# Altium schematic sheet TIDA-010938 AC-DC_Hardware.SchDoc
size 431 x 279 mm; Date: Not shown in title block; ApprovedBy: Not shown in title block; CheckedBy: Not shown in title block; Author: Not shown in title block; CompanyName: Not shown in title block; Engineer: Not shown in title block; Organization: Not shown in title block; Address1: Not shown in title block; Address2: Not shown in title block; Address3: Not shown in title block; Address4: Not shown in title block; DocumentNumber: 11; Revision: Use project parameter SCH_Rev; SheetNumber: 11; SheetTotal: 11; PageSetup: Record=PageOptions¦CenterHorizontal=True¦CenterVertical=True¦PrintScale=1.00¦XCorrection=1.00¦YCorrection=1.00¦PrintKind=0¦BorderSize=5000000¦LeftOffset=0¦BottomOffset=0¦Orientation=2¦PaperLength=1000¦PaperWidth=1000¦Scale=100¦PaperSource=15¦PrintQuality=600¦MediaType=1¦DitherType=10¦PaperKind=Letter¦PrintScaleMode=1
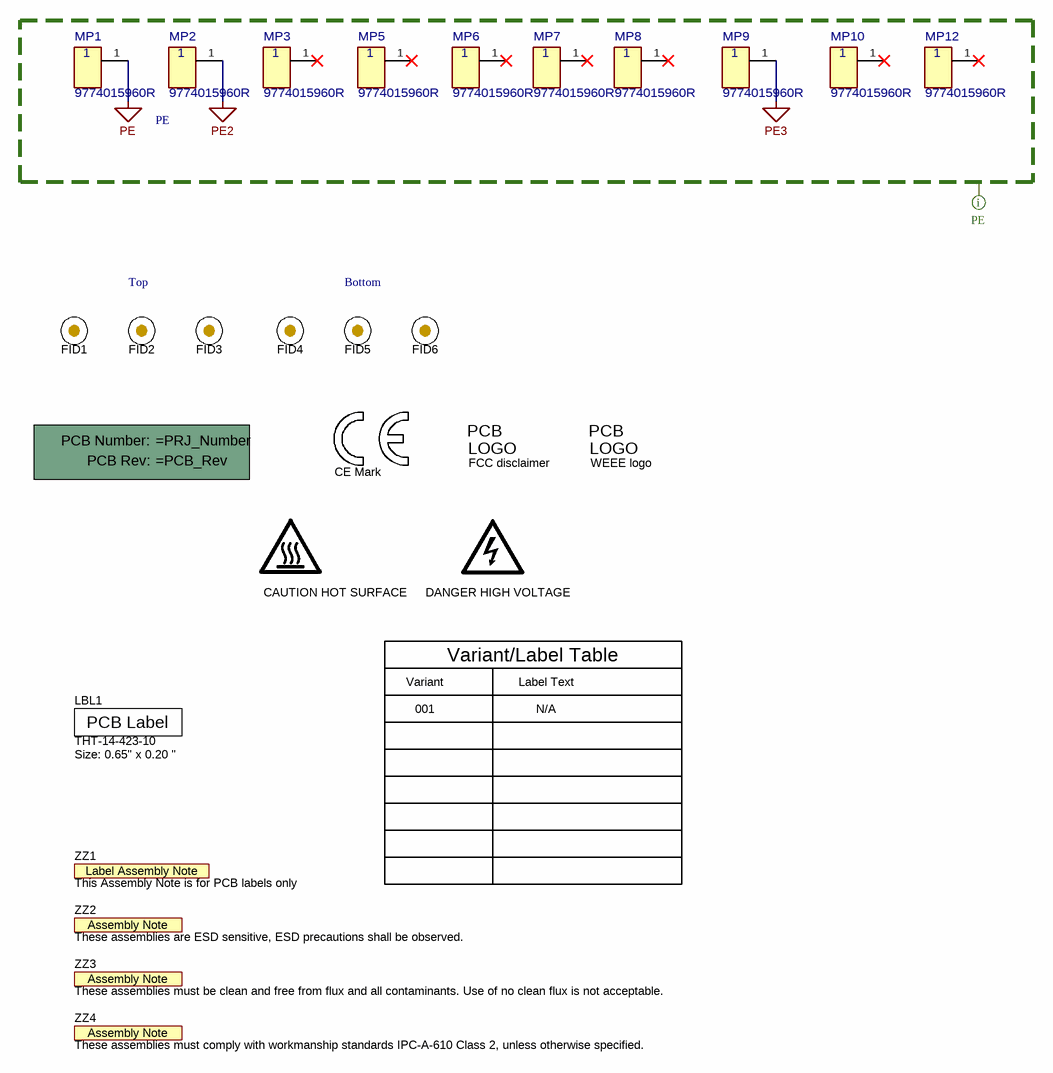
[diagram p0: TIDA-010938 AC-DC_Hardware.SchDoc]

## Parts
!PCB1  Printed Circuit Board  (value not drawn)  (mechanical)
FID1  Fiducial  [Fiducial10-20]  (value not drawn)
FID2  Fiducial  [Fiducial10-20]  (value not drawn)
FID3  Fiducial  [Fiducial10-20]  (value not drawn)
FID4  Fiducial  [Fiducial10-20]  (value not drawn)
FID5  Fiducial  [Fiducial10-20]  (value not drawn)
FID6  Fiducial  [Fiducial10-20]  (value not drawn)
LBL1  THT-14-423-10  Note: Size: 0.65" x 0.20 "  [Label_650x200]
LOGO1  CAUTION HOT SURFACE  [IEC_HotSurface_Small]  (no BOM)
LOGO2  DANGER HIGH VOLTAGE  [IEC_HighVoltage_Small]  (no BOM)
Logo3  CE Mark  [CE_Mark_5mm]  (no BOM)
Logo5  FCC disclaimer  [FCC_disclaimer]  (no BOM)
Logo6  WEEE logo  [WEEE_Minimum]  (no BOM)
MP1  9774015960R  [FP-9774015960R_ROUND_SPACER_6MM0-MFG]
MP2  9774015960R  [FP-9774015960R_ROUND_SPACER_6MM0-MFG]
MP3  9774015960R  [FP-9774015960R_ROUND_SPACER_6MM0-MFG]
MP5  9774015960R  [FP-9774015960R_ROUND_SPACER_6MM0-MFG]
MP6  9774015960R  [FP-9774015960R_ROUND_SPACER_6MM0-MFG]
MP7  9774015960R  [FP-9774015960R_ROUND_SPACER_6MM0-MFG]
MP8  9774015960R  [FP-9774015960R_ROUND_SPACER_6MM0-MFG]
MP9  9774015960R  [FP-9774015960R_ROUND_SPACER_6MM0-MFG]
MP10  9774015960R  [FP-9774015960R_ROUND_SPACER_6MM0-MFG]
MP12  9774015960R  [FP-9774015960R_ROUND_SPACER_6MM0-MFG]
ZZ1  This Assembly Note is for PCB labels only  [AssemblyNoteLabel]  (no BOM)
ZZ2  These assemblies are ESD sensitive, ESD precautions shall be observed.  [AssemblyNote]  (no BOM)
ZZ3  These assemblies must be clean and free from flux and all contaminants. Use of no clean flux is not acceptable.  [AssemblyNote]  (no BOM)
ZZ4  These assemblies must comply with workmanship standards IPC-A-610 Class 2, unless otherwise specified.  [AssemblyNote]  (no BOM)

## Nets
PE: MP1.1
PE2: MP2.1
PE3: MP9.1

Not connected (* = marked no-connect by the designer): MP3 1*; MP5 1*; MP6 1*; MP7 1*; MP8 1*; MP10 1*; MP12 1*

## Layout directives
net class PE: PE, PE2, PE3

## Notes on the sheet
- PE
- (near FID2) Top
- Bottom
- Variant
- Variant/Label Table
- Label Text
- 001
- N/A

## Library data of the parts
!PCB1 = CMP-0003618-2: Manufacturer: Any
FID1-FID6 = CMP-0077181-1: Fiducial mark.  There is nothing to buy or mount.
LBL1 = CMP-0003625-1: Thermal Transfer Printable Labels, 0.650" W x 0.200" H - 10,000 per roll; Manufacturer: Brady; CompType: Label
LOGO1 = CMP-0074837-1: IEC 61010-1 Hot Surface Warning; SymbolCreator: a0412235; Lib Reference: IEC_HotSurface
LOGO2 = CMP-0074835-1: IEC 61010-1 High Voltage Warning; SymbolCreator: a0412235; Lib Reference: IEC_HighVoltage
Logo3 = CMP-0074844-1: SymbolCreator: a0412235
Logo5 = CMP-0074847-1: FCC_disclaimer; Library Reference: Logo
Logo6 = CMP-0074769-1
MP1-MP3 MP5-MP10 MP12 = CMP-0040203-1: Round Spacer Unthreaded Steel 0.059" (1.50mm); Manufacturer: Wurth Electronics; AEC Qualified: No; Is Female: yes; SizeZ_mm: 1.6mm
ZZ1 = CMP-0003616-3
ZZ2 = CMP-0077236-1
ZZ3 = CMP-0077237-1
ZZ4 = CMP-0077238-1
